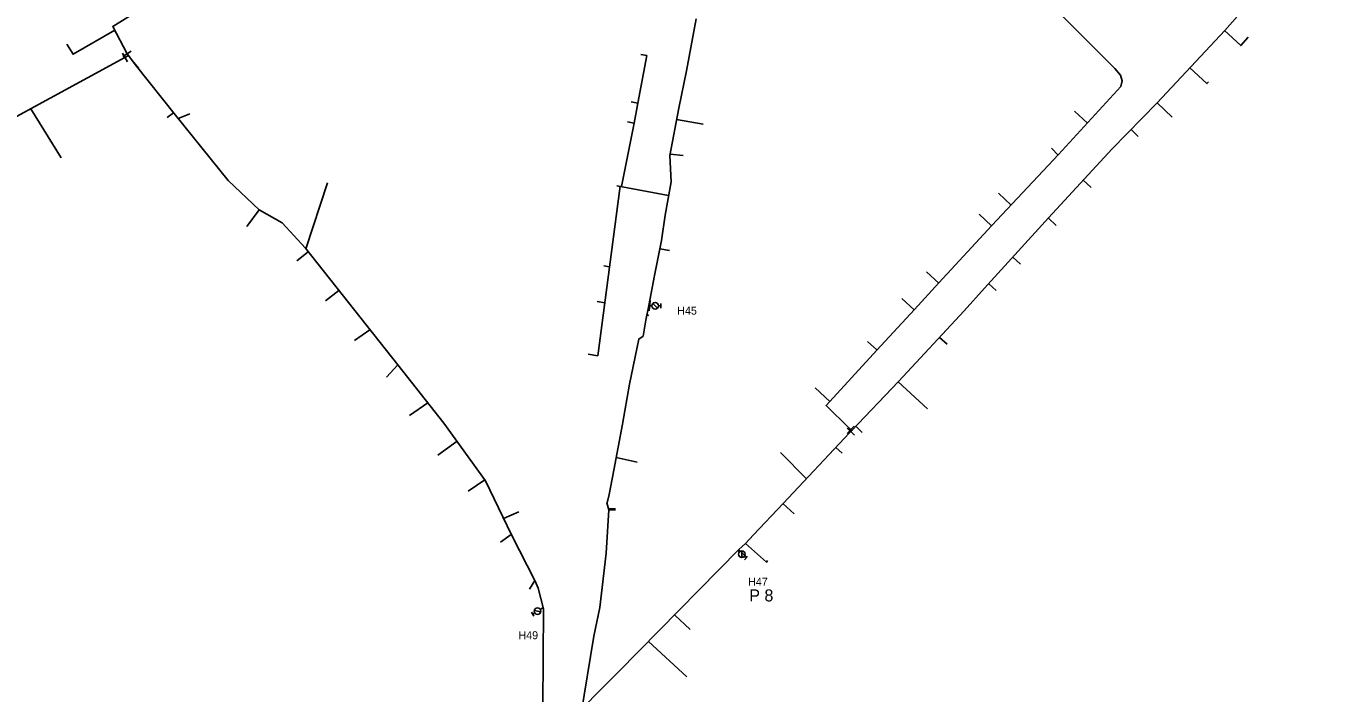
# Model space of a CAD drawing. Extents: x -548873 to -538270, y -1201997 to -1192514.
# Drawn here: x -547630.3 to -547306.8, y -1196082.6 to -1195915.9 of the extents above; entities that cross this region are included whole.
import ezdxf

# ---------------------------------------------------------------- set-up
doc = ezdxf.new("R2010")
doc.units = 0
for name, color, linetype in [('KN_HRAN_STÁTNÍ', 7, 'Continuous'), ('KN_PARC_Č', 7, 'Continuous'), ('KN_VKP_HRAN_SPORNÁ', 7, 'Continuous'), ('PK_PARC_Čv', 7, 'Continuous'), ('Vrstva 29', 7, 'Continuous')]:
    doc.layers.add(name, color=color, linetype=linetype)

# ---------------------------------------------------------------- blocks, each defined once
blk = doc.blocks.new('147')
at = {"layer": 'KN_HRAN_STÁTNÍ'}
blk.add_line((0, 1.27), (0, -1.27), dxfattribs=at)
blk = doc.blocks.new('160')
at = {"layer": 'KN_HRAN_STÁTNÍ'}
blk.add_circle((0, 0), 0.0458, dxfattribs=at)
blk = doc.blocks.new('133')
at = {"layer": 'KN_HRAN_STÁTNÍ'}
for p, q in [((0.28, 0), (0, 0)), ((0.54, 0.58), (1.7, -0.58)), ((1.94, 0), (2.52, 0)), ((2.52, 0.58), (2.52, -0.58))]:
    blk.add_line(p, q, dxfattribs=at)
blk.add_circle((1.11, 0), 0.825, dxfattribs=at)
blk = doc.blocks.new('150')
at = {"layer": 'KN_HRAN_STÁTNÍ'}
blk.add_line((0, 1.27), (0, -1.27), dxfattribs=at)

msp = doc.modelspace()

# ---------------------------------------------------------------- linework, layer by layer
at = {"layer": 'KN_PARC_Č'}
for points in [[(-547608.119, -1195916.946), (-547618.55, -1195922.959), (-547620.114, -1195920.423)], [(-547330.656, -1195917.058), (-547326.637, -1195920.79), (-547324.765, -1195918.679)], [(-547477.34, -1195935.142), (-547475.137, -1195923.279), (-547476.583, -1195922.977)], [(-547339.331, -1195926.322), (-547335.076, -1195930.274), (-547334.671, -1195929.842)], [(-547478.263, -1195940.15), (-547477.34, -1195935.142), (-547479.008, -1195934.822)], [(-547347.556, -1195935.105), (-547343.75, -1195938.71)], [(-547629.131, -1195936.628), (-547621.512, -1195948.836)], [(-547593.403, -1195937.608), (-547594.99, -1195938.791)], [(-547592.207, -1195939.104), (-547591.883, -1195938.821), (-547589.333, -1195937.809)], [(-547467.668, -1195939.274), (-547461.042, -1195940.464)], [(-547364.969, -1195940.147), (-547368.156, -1195937.172)], [(-547481.392, -1195956.03), (-547478.263, -1195940.15), (-547479.953, -1195939.848)], [(-547354.057, -1195941.767), (-547352.296, -1195943.507)], [(-547469.291, -1195947.887), (-547466.019, -1195948.262)], [(-547372.29, -1195948.129), (-547373.944, -1195946.445)], [(-547560.336, -1195971.551), (-547554.96, -1195955.08)], [(-547481.796, -1195955.954), (-547487.359, -1195998.301), (-547489.753, -1195997.869)], [(-547469.661, -1195958.262), (-547482.572, -1195955.806)], [(-547366.014, -1195954.444), (-547363.998, -1195956.262)], [(-547384.036, -1195960.639), (-547387.217, -1195957.688)], [(-547572.003, -1195961.849), (-547575.085, -1195965.99)], [(-547388.901, -1195965.82), (-547392.048, -1195962.912)], [(-547374.722, -1195963.878), (-547372.728, -1195965.714)], [(-547471.84, -1195971.583), (-547469.462, -1195972.024)], [(-547559.745, -1195972.296), (-547562.575, -1195974.607)], [(-547383.633, -1195973.693), (-547381.701, -1195975.4)], [(-547484.443, -1195976.104), (-547485.881, -1195975.845)], [(-547402.124, -1195980.109), (-547405.213, -1195977.305)], [(-547389.634, -1195980.302), (-547387.781, -1195981.979)], [(-547552.103, -1195981.943), (-547555.451, -1195984.523)], [(-547485.625, -1195985.102), (-547487.482, -1195984.757)], [(-547408.279, -1195986.842), (-547411.355, -1195984.022)], [(-547475.065, -1195988.101), (-547474.581, -1195988.202)], [(-547544.308, -1195991.782), (-547548.163, -1195994.483)], [(-547417.587, -1195996.848), (-547419.927, -1195994.74)], [(-547401.93, -1195993.692), (-547400.042, -1195995.41)], [(-547537.333, -1196000.587), (-547540.176, -1196003.613)], [(-547429.353, -1196009.675), (-547433.01, -1196006.306)], [(-547412.233, -1196004.783), (-547404.959, -1196011.552)], [(-547529.852, -1196010.031), (-547534.461, -1196013.255)], [(-547422.844, -1196015.902), (-547421.297, -1196017.436)], [(-547522.554, -1196019.646), (-547527.312, -1196023.13)], [(-547482.77, -1196023.736), (-547477.474, -1196024.87)], [(-547435.168, -1196029.014), (-547441.697, -1196022.497)], [(-547427.827, -1196021.194), (-547426.271, -1196022.647)], [(-547515.583, -1196029.302), (-547519.73, -1196032.13)], [(-547484.682, -1196036.519), (-547482.904, -1196036.51)], [(-547484.617, -1196036.746), (-547482.956, -1196036.796)], [(-547441.04, -1196035.271), (-547438.233, -1196037.772)], [(-547510.894, -1196038.961), (-547507.096, -1196037.265)], [(-547508.991, -1196042.927), (-547511.683, -1196044.893)], [(-547450.435, -1196045.175), (-547445.222, -1196049.864), (-547444.905, -1196049.453)], [(-547452.156, -1196046.712), (-547450.106, -1196048.603)], [(-547503.078, -1196054.473), (-547504.412, -1196056.587)], [(-547468.156, -1196063.016), (-547464.255, -1196066.714)], [(-547474.705, -1196069.689), (-547465.128, -1196078.483)]]:
    msp.add_lwpolyline(points, dxfattribs=at)
at = {"layer": 'KN_VKP_HRAN_SPORNÁ'}
for points in [[(-547508.598, -1195859.206), (-547538.573, -1195874.322), (-547553.093, -1195882.771), (-547564.445, -1195889.747), (-547576.129, -1195896.724), (-547599.306, -1195910.271), (-547608.605, -1195916.011), (-547605.041, -1195922.864)], [(-547424.144, -1196016.765), (-547424.508, -1196016.405), (-547430.282, -1196010.688), (-547417.621, -1195996.885), (-547408.207, -1195986.765), (-547402.107, -1195980.091), (-547388.859, -1195965.775), (-547372.176, -1195948.007), (-547363.002, -1195938.001), (-547356.605, -1195931.025), (-547356.251, -1195929.577), (-547356.667, -1195928.147), (-547358.105, -1195926.546), (-547360.459, -1195924.19), (-547400.597, -1195884.014), (-547408.612, -1195875.991)], [(-547423.899, -1196017.008), (-547412.145, -1196004.69), (-547395.753, -1195987.042), (-547390.663, -1195981.436), (-547374.686, -1195963.838), (-547358.776, -1195946.603), (-547347.545, -1195935.094), (-547330.623, -1195917.023), (-547319.187, -1195904.069), (-547302.312, -1195886.45), (-547300.97, -1195886.17), (-547298.561, -1195886.625), (-547294.438, -1195888.916), (-547286.694, -1195896.655), (-547278.196, -1195905.147)], [(-547462.732, -1195914.137), (-547465.207, -1195927.077), (-547467.132, -1195936.432), (-547469.36, -1195948.254), (-547469.039, -1195954.836), (-547470.544, -1195963.131), (-547471.416, -1195969.45), (-547473.167, -1195978.254), (-547474.624, -1195985.749), (-547475.316, -1195989.435), (-547476.057, -1195993.383), (-547477.134, -1195994.101), (-547479.431, -1196005.39), (-547481.214, -1196015.42), (-547483.35, -1196026.835), (-547484.518, -1196032.936), (-547484.904, -1196034.742), (-547485.099, -1196035.046), (-547484.614, -1196036.758), (-547485.277, -1196047.597), (-547486.862, -1196061.149), (-547488.33, -1196068.353), (-547491.6, -1196088.172)], [(-547604.708, -1195923.286), (-547605.577, -1195923.761)], [(-547605.041, -1195922.864), (-547604.708, -1195923.286)], [(-547604.708, -1195923.286), (-547602.973, -1195925.484)], [(-547605.577, -1195923.761), (-547633.556, -1195939.045)], [(-547602.973, -1195925.484), (-547592.935, -1195938.201), (-547579.777, -1195954.513), (-547572.003, -1195961.849), (-547566.241, -1195965.099), (-547560.467, -1195971.385), (-547537.333, -1196000.587), (-547525.828, -1196015.11), (-547515.419, -1196029.53), (-547508.939, -1196043.036), (-547503.018, -1196054.589), (-547502.297, -1196056.355), (-547500.915, -1196061.504), (-547501.127, -1196085.869), (-547500.777, -1196087.776)], [(-547491.126, -1196094.326), (-547491.939, -1196093.743), (-547492.702, -1196092.165), (-547492.94, -1196090.347), (-547492.732, -1196088.932), (-547492.246, -1196088.04), (-547491.874, -1196087.357), (-547491.162, -1196086.373), (-547490.322, -1196085.494), (-547487.518, -1196082.609), (-547482.336, -1196077.465), (-547477.022, -1196072.05), (-547452.12, -1196046.675), (-547450.412, -1196045.155), (-547448.428, -1196043.063), (-547441.004, -1196035.233), (-547424.435, -1196017.579), (-547424.099, -1196017.221)], [(-547423.899, -1196017.008), (-547424.144, -1196016.765)], [(-547424.099, -1196017.221), (-547423.899, -1196017.008)]]:
    msp.add_lwpolyline(points, dxfattribs=at)
at = {"layer": 'PK_PARC_Čv'}
for points in [[(-547474.624, -1195985.749), (-547474.387, -1195985.781), (-547474.113, -1195985.786)], [(-547452.374, -1196046.934), (-547452.209, -1196047.093), (-547452.169, -1196047.131)], [(-547500.99, -1196061.226), (-547501.478, -1196061.52)]]:
    msp.add_lwpolyline(points, dxfattribs=at)

# ---------------------------------------------------------------- block references
for name, p, xscale, yscale, rotation in [('150', (-547474.387, -1195985.781), 1.0000000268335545, 1.0000000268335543, -3.9999997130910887), ('133', (-547474.113, -1195985.786), 1.000000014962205, 1.0000000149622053, -0.9999999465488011), ('133', (-547452.169, -1196047.131), 1.00000000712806, 1.00000000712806, -43.0000005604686), ('133', (-547501.478, -1196061.52), 0.9999999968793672, 0.9999999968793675, -147.99999972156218)]:
    msp.add_blockref(name, p, dxfattribs=dict(at, xscale=xscale, yscale=yscale, rotation=rotation))
at = {"layer": 'Vrstva 29'}
for name, p, xscale, yscale, rotation in [('147', (-547605.577, -1195923.761), 1.0037042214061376, 1.0037042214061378, 29.379208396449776), ('147', (-547605.041, -1195922.864), 0.9999999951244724, 0.9999999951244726, 123.00000127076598), ('160', (-547604.708, -1195923.286), 1.000000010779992, 1.0000000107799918, 128.99999891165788), ('147', (-547602.973, -1195925.484), 1.000000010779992, 1.0000000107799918, 38.9999989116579), ('147', (-547424.099, -1196017.221), 1.00000000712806, 1.00000000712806, -133.00000056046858), ('147', (-547424.144, -1196016.765), 1.0000000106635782, 1.0000000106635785, 135.99999834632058), ('160', (-547423.899, -1196017.008), 1.00000001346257, 1.0000000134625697, -88.00000009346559)]:
    msp.add_blockref(name, p, dxfattribs=dict(at, xscale=xscale, yscale=yscale, rotation=rotation))

# ---------------------------------------------------------------- texts
at = {"layer": 'PK_PARC_Čv'}
for s, height, p in [('H45', 2, (-547467.503, -1195988.016)), ('H47', 2, (-547449.779, -1196055.751)), ('P 8', 3, (-547449.489, -1196059.671)), ('H49', 2, (-547507.188, -1196069.11))]:
    msp.add_text(s, height=height, dxfattribs=at).set_placement(p)

doc.saveas('drawing.dxf')
